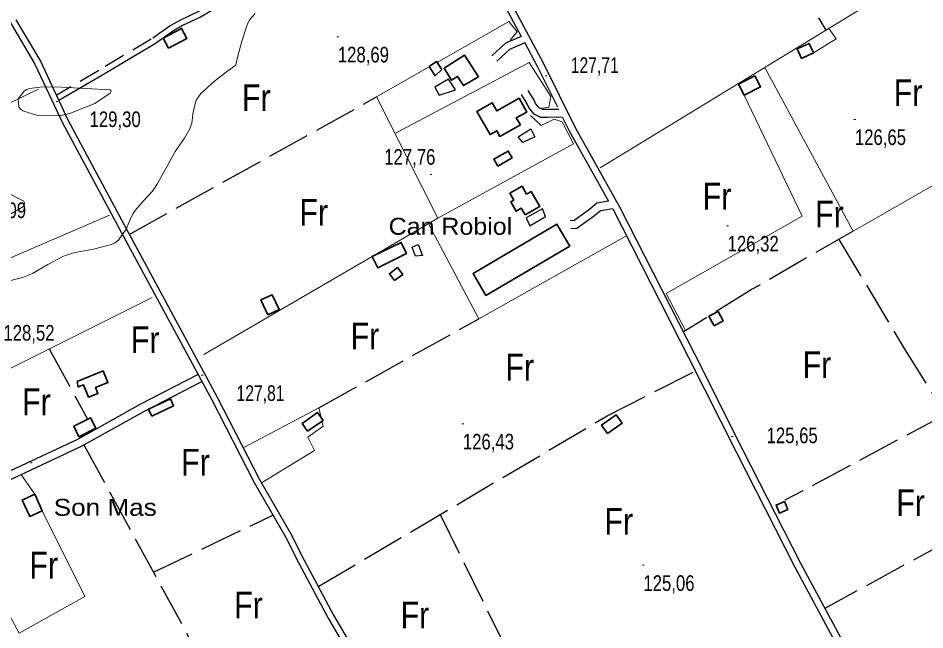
# Model space of a CAD drawing. Extents: x 483855 to 488461, y 4388206 to 4391419.
# Drawn here: x 485739 to 486246, y 4390091 to 4390433 of the extents above; entities that cross this region are included whole.
import ezdxf
from ezdxf.enums import TextEntityAlignment as Align

# ---------------------------------------------------------------- set-up
doc = ezdxf.new("R2010")
doc.units = 0
doc.header["$LTSCALE"] = 4
doc.linetypes.add('LONG_DASHED', pattern=[7.5, 6, -1.5])
doc.linetypes.add('MEDIUM_DASHED', pattern=[4.5, 3, -1.5])
for name, color, linetype, lineweight in [('15', 7, 'LONG_DASHED', 13), ('21', 7, 'Continuous', 25), ('25', 7, 'LONG_DASHED', 25), ('36', 7, 'Continuous', 25), ('38', 7, 'Continuous', 25), ('47', 7, 'Continuous', 35), ('51', 7, 'Continuous', 13), ('7', 7, 'Continuous', 13), ('9', 7, 'Continuous', 13)]:
    doc.layers.add(name, color=color, linetype=linetype, lineweight=lineweight)
doc.layers.add('31', color=7, linetype='Continuous')
doc.layers.add('5', color=7, linetype='Continuous')

msp = doc.modelspace()

# ---------------------------------------------------------------- linework, layer by layer
at = {"layer": '15'}
msp.add_spline([(485988.87, 4391068.04), (485998.94, 4391057.53), (486002.33, 4391047.56), (486012.93, 4391033.93), (486019.04, 4391018.41), (486024.68, 4391004.24), (486026.36, 4390989.16), (486034.27, 4390970.72), (486040.06, 4390957.76), (486055.39, 4390945.7), (486063.13, 4390937.91), (486072.53, 4390923.6), (486082.62, 4390897.51), (486087.3, 4390877.34), (486091.75, 4390862.42), (486096.21, 4390844.8), (486096.99, 4390827.85), (486098.36, 4390814.05), (486099.06, 4390797.32), (486099.09, 4390782.99), (486099.7, 4390771.74), (486102.73, 4390756.37), (486111.25, 4390727.28), (486119.61, 4390707.19), (486127.67, 4390687.77), (486136.4, 4390670.46), (486146.49, 4390645.57), (486156.89, 4390619.63), (486172.84, 4390590.93), (486180.89, 4390576.54), (486187.22, 4390560.95), (486197.89, 4390546.04), (486213.23, 4390527.23), (486226.52, 4390514.2), (486236.37, 4390501.62), (486250.72, 4390486.71), (486261.18, 4390471.95), (486270.65, 4390455.91), (486275.7, 4390444), (486279.62, 4390432.82), (486283.84, 4390419.48), (486289.04, 4390402.23), (486297.99, 4390388.75), (486298.93, 4390369.09), (486300.23, 4390352.82), (486312.94, 4390328.76), (486321.38, 4390309.79), (486332.06, 4390289.33), (486336.71, 4390248.61), (486341.19, 4390211.18), (486345.81, 4390187.19), (486347.48, 4390172.64), (486347.21, 4390157.78), (486346.26, 4390140.53), (486338.86, 4390126.19), (486336.32, 4390120.03), (486336.26, 4390105.41), (486340.56, 4390096.04), (486348.38, 4390083.82), (486353.34, 4390075.2), (486354.36, 4390073.3)], degree=3, dxfattribs=at)
at = {"layer": '21'}
for points in [[(485974.31, 4390390.02), (485983.38, 4390393.03), (485979.62, 4390399.03), (485971.82, 4390394.51)], [(486018.53, 4390366.76), (486025.57, 4390371.2), (486027.9, 4390366.63), (486021.08, 4390363.54)], [(486025.06, 4390316.89), (486033.83, 4390322), (486032.17, 4390326.42), (486022.95, 4390321.38)], [(485961.18, 4390299.75), (485959.22, 4390304.93), (485962.59, 4390306.36), (485965, 4390300.21)]]:
    msp.add_lwpolyline(points, close=True, dxfattribs=at)
at = {"layer": '25'}
for p, q in [((486140.58, 4390510.66), (486190.7, 4390426.39)), ((485800.93, 4390312.05), (485939.2, 4390388.98)), ((485907.08, 4390214.9), (485996.49, 4390264.78)), ((485756.18, 4390247.9), (485777.63, 4390208.51)), ((485775.56, 4390194.14), (485858.6, 4390041.91)), ((486339.72, 4390184.31), (486190.15, 4390102.55)), ((485814.49, 4390122.79), (485881.3, 4390154.81)), ((485974.88, 4390155.12), (486024.98, 4390053.39))]:
    msp.add_line(p, q, dxfattribs=at)
for points in [[(486205.92, 4390313.81), (486149.57, 4390281.31), (486110.94, 4390257.35)], [(486198.02, 4390309.26), (486234.01, 4390249.12), (486254.24, 4390216.52)], [(486327.97, 4390263.04), (486254.24, 4390216.52), (486257.18, 4390210.82), (486167.69, 4390163.12)], [(485906.67, 4390114.79), (486068.29, 4390210.36), (486117.66, 4390235.55)]]:
    msp.add_lwpolyline(points, dxfattribs=at)
at = {"layer": '36'}
for points in [[(485734.49, 4390430.51), (485748.11, 4390407.42), (485763.54, 4390374.59), (485779.94, 4390343.94), (485796.35, 4390313.29), (485818.69, 4390271.84)], [(485737.47, 4390432.24), (485751.16, 4390409.03), (485766.62, 4390376.13), (485782.97, 4390345.56), (485799.38, 4390314.92), (485821.72, 4390273.47)], [(485737.47, 4390432.24), (485751.16, 4390409.03), (485766.62, 4390376.13), (485782.97, 4390345.56), (485799.38, 4390314.92), (485821.72, 4390273.47)], [(485818.69, 4390271.84), (485847.14, 4390219.3), (485870.77, 4390173.13), (485888.29, 4390142.63), (485895.75, 4390127.94), (485912.22, 4390097.06), (485927.95, 4390070.16), (485931.11, 4390061.46), (485934.34, 4390058.24), (485939.46, 4390053.47)], [(485821.72, 4390273.48), (485850.19, 4390220.9), (485873.8, 4390174.77), (485891.32, 4390144.27), (485898.8, 4390129.53), (485915.22, 4390098.74), (485931.08, 4390071.63), (485934.08, 4390063.36), (485936.73, 4390060.72), (485940.02, 4390057.65), (485944.19, 4390054.03)], [(485821.72, 4390273.48), (485850.19, 4390220.9), (485873.8, 4390174.77), (485891.32, 4390144.27), (485898.8, 4390129.53), (485915.22, 4390098.74), (485931.08, 4390071.63), (485934.08, 4390063.36), (485936.73, 4390060.72), (485940.02, 4390057.65), (485941.24, 4390056.59)]]:
    msp.add_lwpolyline(points, dxfattribs=at)
at = {"layer": '38'}
for points in [[(485882.55, 4390700.43), (485900.14, 4390663.7), (485924.9, 4390615.66), (485954.25, 4390556.37), (485976.45, 4390515.75), (486007.98, 4390454.21), (486032.58, 4390408.05), (486050.65, 4390371.54), (486075.32, 4390327.4), (486117.32, 4390244.8), (486144.11, 4390191.66), (486176.54, 4390127.88), (486210.03, 4390065.51), (486215.81, 4390056.99), (486217.3, 4390050.5)], [(485974.14, 4390511.77), (485952.55, 4390499.22), (485891.18, 4390464.01), (485851.47, 4390439.79), (485840.81, 4390433.7), (485830.77, 4390428.95), (485825.68, 4390426.02), (485815.04, 4390418.58), (485785.52, 4390400.97), (485761.59, 4390386.95)], [(485974.14, 4390511.77), (486004.55, 4390452.42), (486020.26, 4390422.94)], [(486022.2, 4390419.31), (486013.68, 4390415.61), (486006.65, 4390409.08)], [(486022.2, 4390419.31), (486029.14, 4390406.28), (486040.47, 4390383.38)], [(486043.39, 4390377.46), (486039.89, 4390377.6), (486035.09, 4390377.51), (486031.26, 4390377.51), (486027.43, 4390379.45), (486024.5, 4390383.05), (486023.52, 4390385.15), (486020.36, 4390390.39)], [(486043.39, 4390377.46), (486047.22, 4390369.74), (486069.08, 4390330.64)], [(486071.49, 4390326.39), (486064.64, 4390325.23), (486061.26, 4390322.37), (486051.46, 4390315.38), (486047.94, 4390315.08)], [(486071.49, 4390326.39), (486113.87, 4390243.05), (486140.66, 4390189.91), (486173.11, 4390126.09), (486206.72, 4390063.51), (486212.2, 4390055.42), (486213.46, 4390049.91)], [(485522.96, 4390277.98), (485525.78, 4390273.13), (485551.98, 4390215.04), (485574.78, 4390168.34), (485598.79, 4390121.87), (485602.05, 4390115.15), (485603.27, 4390114.39), (485605.43, 4390114.78), (485610.29, 4390117.06), (485632.55, 4390131.12), (485667.48, 4390146.71), (485697.83, 4390162.74), (485734.63, 4390179.83), (485772.19, 4390197.44), (485807.34, 4390217.08), (485839.38, 4390233.64)], [(485732.44, 4390173.82), (485736.54, 4390175.73), (485774.26, 4390193.41), (485809.49, 4390213.09), (485841.46, 4390229.62)]]:
    msp.add_lwpolyline(points, dxfattribs=at)
at = {"layer": '38', "linetype": 'MEDIUM_DASHED'}
for points in [[(485972.61, 4390514.7), (485950.9, 4390502.08), (485889.49, 4390466.85), (485849.79, 4390442.63), (485839.28, 4390436.63), (485829.24, 4390431.88), (485823.9, 4390428.81), (485813.24, 4390421.36), (485783.83, 4390403.81), (485760.3, 4390390.02)], [(486020.26, 4390422.94), (486011.4, 4390419.1), (486003.85, 4390412.09)], [(486041.37, 4390381.94), (486039.94, 4390382), (486035.05, 4390381.91), (486032.31, 4390381.91), (486030.25, 4390382.95), (486028.26, 4390385.41), (486027.41, 4390387.22), (486024.13, 4390392.66)], [(486069.08, 4390330.64), (486062.63, 4390329.55), (486058.44, 4390326), (486049.82, 4390319.85), (486047.55, 4390319.66)]]:
    msp.add_lwpolyline(points, dxfattribs=at)
at = {"layer": '38', "linetype": 'LONG_DASHED'}
msp.add_spline([(486193.4, 4390565.76), (486212.3, 4390545.54), (486236.35, 4390513.02), (486254.31, 4390495.34), (486265.36, 4390479.16), (486280.33, 4390458.48), (486285.22, 4390447.54), (486290.89, 4390422.12), (486299.92, 4390402.33), (486303.42, 4390375.85), (486309.68, 4390352.53), (486321.88, 4390323.15), (486327.83, 4390311.08)], degree=3, dxfattribs=at)
at = {"layer": '47'}
for points in [[(485822.81, 4390416.32), (485833.16, 4390421.78), (485830.22, 4390427.36), (485819.87, 4390421.9)], [(486177.03, 4390410.6), (486183.8, 4390413.69), (486181.37, 4390419.01), (486174.6, 4390415.92)], [(485975.78, 4390404.42), (485972.92, 4390408.77), (485968.69, 4390405.99), (485972.04, 4390400.88)], [(485996.27, 4390400.25), (485988.6, 4390412.39), (485977.04, 4390405.1), (485981.3, 4390398.33), (485984.68, 4390400.46), (485987.9, 4390395.34)], [(486144.96, 4390389.92), (486154.18, 4390394.62), (486151.02, 4390400.81), (486141.8, 4390396.11)], [(486019.87, 4390373.36), (486008.32, 4390366.89), (486006.55, 4390370.03), (486002.79, 4390367.92), (485995.47, 4390380.94), (486004.03, 4390385.77), (486006.59, 4390381.22), (486019.06, 4390388.25), (486023.38, 4390380.56), (486017.51, 4390377.27)], [(486007.08, 4390350.31), (486015.16, 4390354.83), (486012.99, 4390358.72), (486004.91, 4390354.2)], [(486022.5, 4390322.96), (486030.59, 4390327.62), (486025.76, 4390335.98), (486023.27, 4390334.56), (486020.75, 4390338.96), (486013.88, 4390335.03), (486016.07, 4390331.19), (486014.38, 4390330.23), (486017.35, 4390324.99), (486020.29, 4390326.65)], [(486047.43, 4390305.45), (486000.49, 4390277.83), (485993.3, 4390290.05), (486040.24, 4390317.67)], [(485956.07, 4390301.25), (485939.96, 4390293.35), (485936.87, 4390299.64), (485952.98, 4390307.54)], [(485949.42, 4390286.16), (485946.48, 4390290.02), (485950.98, 4390293.44), (485953.92, 4390289.58)], [(485878.49, 4390266.99), (485874.58, 4390275.32), (485880.8, 4390278.24), (485884.71, 4390269.91)], [(486128.15, 4390260.87), (486133.21, 4390263.54), (486130.38, 4390268.9), (486125.32, 4390266.23)], [(485771.73, 4390229.61), (485786.27, 4390235.56), (485788.95, 4390229), (485782.09, 4390226.2), (485783.38, 4390223.02), (485778.11, 4390220.89), (485775.3, 4390227.82), (485772.26, 4390226.59)], [(485811.74, 4390214.22), (485823.92, 4390219.95), (485825.76, 4390216.04), (485813.58, 4390210.31)], [(485900.65, 4390201.76), (485909.36, 4390207.89), (485906.33, 4390212.2), (485897.62, 4390206.07)], [(486068.61, 4390200.46), (486076.73, 4390206.31), (486073.32, 4390211.05), (486065.2, 4390205.2)], [(485782.2, 4390203.44), (485772.75, 4390198.73), (485769.82, 4390204.62), (485779.27, 4390209.33)], [(485748.05, 4390166.48), (485752.24, 4390157.3), (485745.22, 4390154.1), (485741.03, 4390163.28)], [(486169.5, 4390158.02), (486167.62, 4390162.45), (486162.82, 4390160.41), (486164.7, 4390155.98)]]:
    msp.add_lwpolyline(points, close=True, dxfattribs=at)
at = {"layer": '51'}
for p, q in [((486064.39, 4390349.28), (486230.23, 4390450.52)), ((485724.4, 4390294.62), (485789.81, 4390322.73)), ((485973.67, 4390321.08), (485937.18, 4390299.8)), ((485936.88, 4390299.62), (485842.74, 4390244.72)), ((485813.74, 4390276.63), (485582.21, 4390161.03)), ((485748.05, 4390166.48), (485740.54, 4390177.27))]:
    msp.add_line(p, q, dxfattribs=at)
for points in [[(486014.09, 4390420.76), (486017.91, 4390425.42), (486013.4, 4390431.34), (485973.19, 4390408.38)], [(486192.32, 4390427.38), (486196.45, 4390421.51), (486183.8, 4390413.69)], [(486031.7, 4390382.68), (486035.68, 4390383.29), (486036.79, 4390389.22), (486024.69, 4390408.25), (485949.54, 4390368.62)], [(485968.75, 4390405.85), (485939.2, 4390388.98), (485973.67, 4390321.08), (486049.51, 4390362.68), (486043.19, 4390374.98), (486038.69, 4390376.47), (486031.42, 4390373.01), (486025.48, 4390378.55)], [(486156.56, 4390405.55), (486205.92, 4390313.81), (486259.73, 4390344.73), (486289.25, 4390361.18)], [(485750.16, 4390393.33), (485599.65, 4390320.77), (485525.9, 4390283.89)], [(486144.96, 4390389.92), (486177.55, 4390322.24), (486101.34, 4390278.98), (486112.02, 4390258.52)], [(485968.42, 4390318.02), (485996.49, 4390264.78), (486078.78, 4390310.97)], [(485864.73, 4390192.5), (485907.08, 4390214.9), (485908.28, 4390209.46)], [(485908.73, 4390207.42), (485909.35, 4390204.63), (485900.88, 4390198.46), (485904.49, 4390190.97), (485874.91, 4390172.84)], [(485701.86, 4390158.23), (485739.25, 4390088.75), (485775.98, 4390109.21), (485752.24, 4390157.3)]]:
    msp.add_lwpolyline(points, dxfattribs=at)
at = {"layer": '7'}
for p, q in [((485917.12, 4390422.71), (485918.12, 4390422.71)), ((486033.57, 4390400.77), (486034.57, 4390400.77)), ((485760.02, 4390386.52), (485761.02, 4390386.52)), ((486206.45, 4390376.45), (486207.45, 4390376.45)), ((485969.23, 4390345.53), (485970.23, 4390345.53)), ((486135.21, 4390316.84), (486136.21, 4390316.84)), ((485841.21, 4390233.17), (485842.21, 4390233.17)), ((485987.08, 4390205.95), (485988.08, 4390205.95)), ((486137.8, 4390198.77), (486138.8, 4390198.77)), ((485745.65, 4390184.1), (485746.65, 4390184.1)), ((486088.11, 4390126.75), (486089.11, 4390126.75))]:
    msp.add_line(p, q, dxfattribs=at)
at = {"layer": '9'}
for points in [[(485871.33, 4390435.8), (485868.32, 4390432.31), (485867.51, 4390430.74), (485866.71, 4390428.92), (485863.93, 4390420.17), (485861.75, 4390411.79), (485861.34, 4390410.18), (485861, 4390408.9), (485860.48, 4390406.86), (485860.48, 4390406.86), (485860.48, 4390406.86), (485860.48, 4390406.86), (485860.48, 4390406.86), (485858.64, 4390405.48), (485857.49, 4390404.62), (485856.05, 4390403.54), (485848.53, 4390397.91), (485841.01, 4390390.99), (485839.57, 4390389.11), (485838.42, 4390387.24), (485836.6, 4390380.58), (485835.87, 4390374.35), (485835.4, 4390372.74), (485834.82, 4390371.18), (485831.78, 4390365.98), (485827.83, 4390360.28), (485826.69, 4390358.41), (485825.51, 4390356.41), (485821.08, 4390348.16), (485816.39, 4390339.93), (485815.05, 4390337.96), (485813.71, 4390336.12), (485808.73, 4390330.58), (485804.18, 4390325.35), (485803.11, 4390323.7), (485802.13, 4390321.98), (485799.23, 4390315.03), (485794.98, 4390308.75), (485793.13, 4390307.45), (485791, 4390306.33)], [(485791, 4390306.33), (485780.87, 4390303.85), (485769.66, 4390301.74), (485766.84, 4390300.85), (485764.14, 4390299.84), (485755.42, 4390295.08), (485746.73, 4390290.14), (485744.05, 4390289), (485741.25, 4390287.97), (485730.16, 4390285.07), (485728.95, 4390284.87)]]:
    msp.add_lwpolyline(points, dxfattribs=at)
for points in [[(485763.09, 4390394.43), (485752.33, 4390394.67), (485745.13, 4390393.76), (485743.56, 4390393.12), (485742.18, 4390392.31), (485738.75, 4390388), (485739.07, 4390383.27), (485740.05, 4390382.2), (485741.43, 4390381.24), (485749.62, 4390378.62), (485761.05, 4390378.47), (485764.46, 4390379.06), (485767.98, 4390379.92), (485781.61, 4390385.31), (485790.31, 4390391.08), (485790.73, 4390392.18), (485790.29, 4390393.07)], [(485714.81, 4390315.57), (485733.17, 4390322.63), (485741.91, 4390327.9), (485742.33, 4390329.28), (485741.9, 4390330.61), (485733.14, 4390335.11), (485719.7, 4390338.08), (485716.31, 4390338.44), (485713.07, 4390338.61), (485702.59, 4390337.57), (485696.79, 4390334.24), (485696.51, 4390332.96), (485696.79, 4390331.53)]]:
    msp.add_lwpolyline(points, close=True, dxfattribs=at)

# ---------------------------------------------------------------- texts
at = {"layer": '31', "width": 0.85}
for p in [(486236.72, 4390383.94), (485872.02, 4390381.14), (486129.82, 4390325.92), (485904.16, 4390316.83), (486192.75, 4390315.92), (485932.8, 4390247.63), (485809.83, 4390245.53), (486185.72, 4390231.55), (486019.43, 4390230.15), (485748.97, 4390210.77), (485837.98, 4390176.94), (486238.12, 4390154.27), (486074.85, 4390143.87), (485753.06, 4390119.32), (485867.64, 4390096.95), (485960.74, 4390091.36)]:
    msp.add_text('Fr', height=15, dxfattribs=at).set_placement(p, align=Align.CENTER)
at = {"layer": '5', "width": 1.1}
msp.add_text('Can Robiol', height=9.5, dxfattribs=at).set_placement((486015.2, 4390311.82), align=Align.RIGHT)
at = {"layer": '5', "width": 1.15}
msp.add_text('Son Mas', height=9.5, dxfattribs=at).set_placement((485758.65, 4390154.42))
at = {"layer": '7'}
for s, width, p in [('128,69', 0.8, (485917.62, 4390408.34)), ('127,71', 0.75, (486047.97, 4390402.45)), ('129,30', 0.8, (485778.7, 4390372.15)), ('126,65', 0.8, (486206.95, 4390362.08)), ('127,76', 0.8, (485943.59, 4390351.05)), ('129,09', 0.8, (485714.55, 4390321.14)), ('126,32', 0.8, (486135.71, 4390302.47)), ('128,52', 0.8, (485730.48, 4390252.53)), ('127,81', 0.75, (485860.95, 4390218.8)), ('126,43', 0.8, (485987.58, 4390191.58)), ('125,65', 0.8, (486157.55, 4390195.1)), ('125,06', 0.8, (486088.61, 4390112.38))]:
    msp.add_text(s, height=8.75, dxfattribs=dict(at, width=width)).set_placement(p)

doc.saveas('drawing.dxf')
